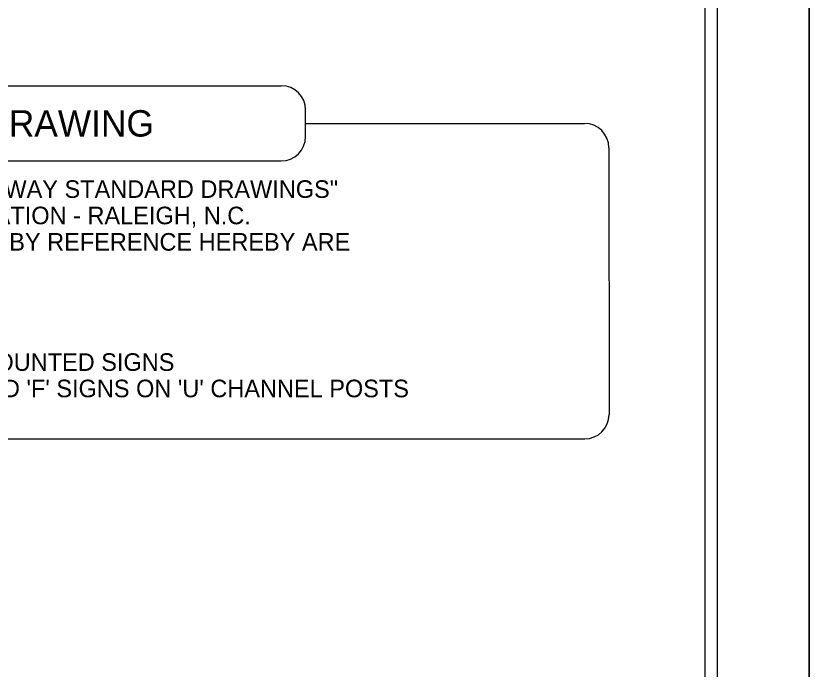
# Model space of a CAD drawing. Extents: x 1359317 to 1361345, y 1001522 to 1002524.
# Drawn here: x 1360569.7 to 1360865, y 1002022.8 to 1002265.9 of the extents above; entities that cross this region are included whole.
import ezdxf

# ---------------------------------------------------------------- set-up
doc = ezdxf.new("R2010")
doc.units = 0
for name, color, linetype in [('Sheet Plot Border Outside CELL', 7, 'Continuous'), ('Sheet_Title_CELL', 7, 'Continuous'), ('Text', 7, 'Continuous'), ('z - Construction', 7, 'Continuous')]:
    doc.layers.add(name, color=color, linetype=linetype)

msp = doc.modelspace()

# ---------------------------------------------------------------- linework, layer by layer
at = {"layer": 'Sheet Plot Border Outside CELL'}
msp.add_lwpolyline([(1359316.74, 1002523.7), (1360865.01, 1002523.7), (1360865.01, 1001521.88), (1359316.74, 1001521.88)], close=True, dxfattribs=at)
at = {"layer": 'Sheet_Title_CELL'}
for p, q in [((1360830.86, 1001565.14), (1360830.86, 1002480.44)), ((1360826.3, 1001569.62), (1360826.3, 1002475.82)), ((1360409.38, 1002239.88), (1360668.47, 1002239.88)), ((1360677.56, 1002221.02), (1360677.56, 1002230.79)), ((1360677.56, 1002225.91), (1360781.36, 1002225.92)), ((1360790.45, 1002216.82), (1360790.55, 1002117.57)), ((1360409.57, 1002211.94), (1360668.47, 1002211.93)), ((1360296.77, 1002108.51), (1360781.46, 1002108.48))]:
    msp.add_line(p, q, dxfattribs=at)
for centre, start, end in [((1360668.48, 1002230.83), 0, 90), ((1360781.36, 1002216.82), 0.0011, 90), ((1360668.47, 1002221.02), 270, 0), ((1360781.46, 1002117.57), 270, 0)]:
    msp.add_arc(centre, 9.09, start, end, dxfattribs=at)
at = {"layer": 'z - Construction'}
msp.add_line((1360865.01, 1001521.88), (1360865.01, 1002523.7), dxfattribs=at)

# ---------------------------------------------------------------- texts
at = {"layer": 'Text'}
msp.add_text('ROADWAY STANDARD DRAWING', height=9.8184, dxfattribs=at).set_placement((1360410.28, 1002221))
for s, p in [('THE FOLLOWING ROADWAY STANDARDS AS APPEAR IN " ROADWAY STANDARD DRAWINGS"', (1360292.44, 1002198.19)), ('PROJECT SERVICES UNIT - N.C. DEPARTMENT OF TRANSPORTATION - RALEIGH, N.C.', (1360292.44, 1002188.37)), ('DATED JANUARY 2024 ARE APPLICABLE TO THIS PROJECT AND BY REFERENCE HEREBY ARE', (1360292.44, 1002178.55)), ('ORIENTATION OF GROUND MOUNTED SIGNS', (1360436.66, 1002133.8)), ("MOUNTING OF TYPE 'D', 'E' AND 'F' SIGNS ON 'U' CHANNEL POSTS", (1360436.66, 1002123.98))]:
    msp.add_text(s, height=6.5456, rotation=359.9975, dxfattribs=at).set_placement(p)

doc.saveas('drawing.dxf')
